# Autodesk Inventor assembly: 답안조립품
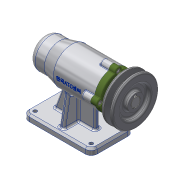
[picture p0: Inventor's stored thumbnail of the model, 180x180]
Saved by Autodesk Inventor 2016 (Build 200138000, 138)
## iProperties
Created: 2019-07
Part Number: 답안조립품
Material: 일반
Document SubType Name: Assembly
Designer: 605-03
Author: 605-03
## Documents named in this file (12)
- C:\Users\605-03\Desktop\490704V1063\답안조립품.iam
- C:\Users\605-03\Desktop\490704V1063\1.본체.ipt
- C:\Users\605-03\Desktop\490704V1063\베어링 6004.ipt
- C:\Users\605-03\Desktop\490704V1063\베어링 51202.ipt
- C:\Users\605-03\Desktop\490704V1063\오일 실.ipt
- C:\Users\605-03\Desktop\490704V1063\축.ipt
- C:\Users\605-03\Desktop\490704V1063\키 5 x 5 x 16.ipt
- C:\Users\605-03\Desktop\490704V1063\어댑터슬리브.ipt
- C:\Users\605-03\Desktop\490704V1063\커버.ipt
- C:\Users\605-03\Desktop\490704V1063\V벨트풀리.ipt
- C:\Users\605-03\Desktop\490704V1063\볼트 M4.ipt
- C:\Users\605-03\Desktop\490704V1063\멈춤나사 M3.ipt
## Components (2 placed, 2 different names)
1. 1.본체:1
2. V벨트풀리:1 — 각도:1
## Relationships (1: Angle 1)
- 각도:1 [Angle]: V벨트풀리:1
